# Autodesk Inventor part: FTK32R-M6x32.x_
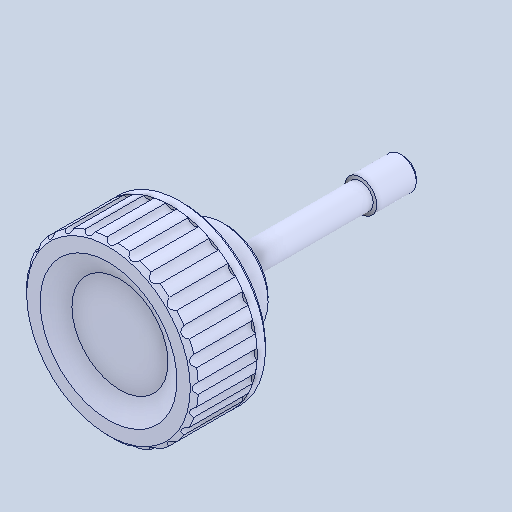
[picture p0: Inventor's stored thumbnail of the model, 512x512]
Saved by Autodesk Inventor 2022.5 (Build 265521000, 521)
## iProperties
Created: 2024-06
Part Number: FTK32R-M6x32.x_
Material: 一般
Document SubType Name: Modeling
Designer: ImaoCorp
Density: 1 g/cm^3
Appearance: 既定
Author: ImaoCorp
Sending System: SOLIDWORKS 2022-2022290
MC: AMD64
MC_MODEL: Intel64 Family 6 Model 60 Stepping 3, GenuineIntel
OS: Windows_NT
FRU: Parasolid Version 33.1, build 260,  4-25-2022
FORMAT: text
GUISE: transmit
KEY: FILEFTK32R-M6x32.x_t
DATE: Fri Jun 28 15:20:33 2024
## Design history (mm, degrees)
feature "Base1"
node "ソリッド1"
